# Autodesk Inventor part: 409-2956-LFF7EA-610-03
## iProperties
Created: 2011-01
Part Number: 409-2956-LFF7EA-610-03
Cost Center: 0 lbmass
Material: A36 STEEL PLATE
Document SubType Name: Sheet Metal
Designer: S. Boerckel
Authority: 0 in^3
Mass: 10143.2 g
Surface Area: 2203.22 cm^2
Volume: 1290.48 cm^3
Density: 7.86 g/cm^3
Flat Pattern Width: 22.86 cm
Flat Pattern Length: 44.45 cm
Flat Pattern Area: 1016.13 cm^2
Sheet Metal Rule: 1/2"Thk
Description: BASE PLATE
SaveDate: 2008-01-15
SaveTime: 10:24
FileName: Sheet Metal
Wide: =<Flat Pattern Width>cm
Length: =<Flat Pattern Length>cm
Thickness: 0.5000 in
SMR: =<Sheet Metal Rule> - <Material>
Author: S. Boerckel
Revision Number: 0
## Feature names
1. Plate1
